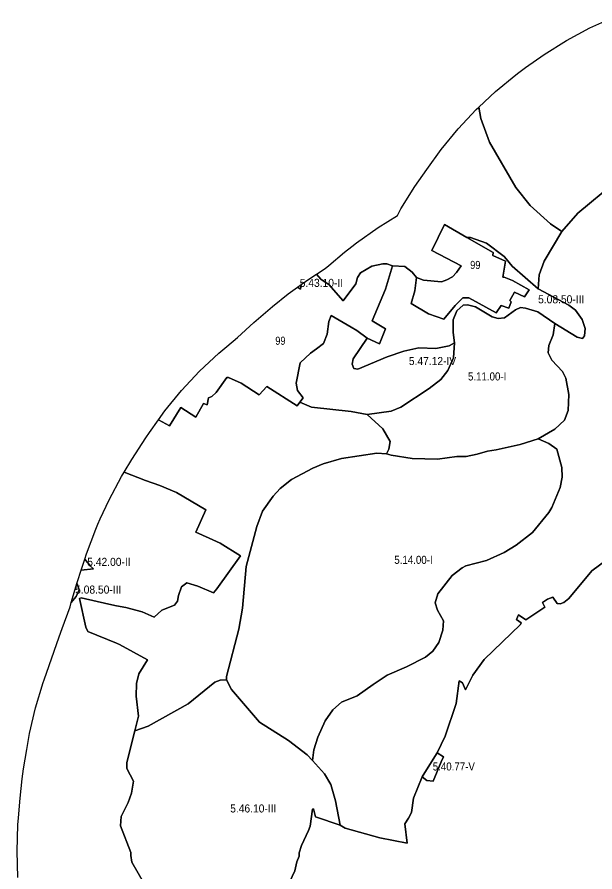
# Model space of a CAD drawing. Extents: x -591496 to -585489, y -1120610 to -1115685.
# Drawn here: x -591496 to -590065, y -1118038 to -1115920 of the extents above; entities that cross this region are included whole.
import ezdxf

# ---------------------------------------------------------------- set-up
doc = ezdxf.new("R2010")
doc.units = 0
doc.header["$LTSCALE"] = 8
doc.layers.add('40', color=7, linetype='Continuous', lineweight=25)
doc.layers.add('41', color=7, linetype='Continuous')

msp = doc.modelspace()

# ---------------------------------------------------------------- linework, layer by layer
at = {"layer": '40'}
for points in [[(-590015, -1116329.5), (-590106.5, -1116406), (-590146.5, -1116451.5), (-590174.5, -1116432), (-590225, -1116387), (-590260.5, -1116342), (-590325.5, -1116229.5), (-590347.5, -1116171), (-590352.159, -1116143.048), (-590311.076, -1116104.57), (-590260.491, -1116063.057), (-590253.1, -1116057.44), (-590236.32, -1116044.81), (-590190.52, -1116012.31), (-590134.95, -1115977.755), (-590077.239, -1115946.907), (-590017.633, -1115919.9)], [(-590130.5, -1116894.5), (-590129.5, -1116855.5), (-590136.5, -1116815), (-590144.5, -1116798), (-590171, -1116770), (-590180, -1116752), (-590178.5, -1116734), (-590168, -1116707), (-590164, -1116679.5), (-590108.5, -1116713), (-590095.5, -1116716.5), (-590090, -1116710), (-590089, -1116692), (-590096.5, -1116669.5), (-590112.5, -1116646.5), (-590129, -1116633.5), (-590205.5, -1116593.5), (-590203, -1116559), (-590190, -1116524.5), (-590146.5, -1116451.5), (-590106.5, -1116406), (-590015, -1116329.5)], [(-590037.5, -1117266.5), (-590072, -1117292), (-590129.5, -1117361), (-590141.5, -1117370.5), (-590150.5, -1117374), (-590158, -1117373), (-590169, -1117357.5), (-590182, -1117362.5), (-590194.5, -1117370.5), (-590188.5, -1117382), (-590236, -1117414), (-590253.5, -1117401), (-590259, -1117413), (-590247, -1117421.5), (-590248.5, -1117425.5), (-590339, -1117512), (-590367, -1117550.5), (-590385, -1117587.5), (-590392.5, -1117570), (-590401, -1117565), (-590408.5, -1117621), (-590435.5, -1117702), (-590455.5, -1117743), (-590457, -1117746), (-590492.5, -1117802.5), (-590514, -1117856), (-590518.5, -1117891), (-590526.5, -1117905.5), (-590535, -1117919), (-590530, -1117967.5), (-590597.5, -1117954), (-590683, -1117930), (-590696, -1117922.5), (-590707, -1117862.5), (-590719, -1117822), (-590734.5, -1117795), (-590764, -1117762.5), (-590760.5, -1117736), (-590751, -1117704.5), (-590732.5, -1117664), (-590713.5, -1117637), (-590692.5, -1117618), (-590653.5, -1117602), (-590614, -1117574), (-590579, -1117550.5), (-590531, -1117530.5), (-590484.5, -1117506.5), (-590466, -1117491), (-590451.5, -1117470), (-590441, -1117439), (-590440, -1117416.5), (-590454.5, -1117389.5), (-590460, -1117371.5), (-590454, -1117349), (-590418.5, -1117304), (-590393.5, -1117285), (-590384, -1117280), (-590333.5, -1117266.5), (-590289, -1117247), (-590260, -1117228.5), (-590219, -1117197.5), (-590179, -1117147.5), (-590171, -1117135), (-590150.5, -1117085.5), (-590145.5, -1117060.5), (-590146.5, -1117036), (-590159, -1116991), (-590179, -1116976.5), (-590205, -1116965.5), (-590164, -1116941), (-590140, -1116918.5), (-590130.5, -1116894.5)], [(-591342.5, -1117339.5), (-591347, -1117324.5), (-591347.697, -1117323.261), (-591346.221, -1117318.278), (-591337.303, -1117290.825), (-591307, -1117287), (-591314.5, -1117281), (-591328.334, -1117263.213), (-591328.261, -1117262.988), (-591324.11, -1117250.491), (-591301.059, -1117189.247), (-591295.803, -1117176.795), (-591289.923, -1117163.125), (-591268.173, -1117115.971), (-591237.325, -1117058.26), (-591231.026, -1117047.945), (-591178, -1117068), (-591142.5, -1117081), (-591101, -1117098.5), (-591028.5, -1117141), (-591053, -1117196), (-591020, -1117211.5), (-590993, -1117223.5), (-590942.5, -1117255), (-591001, -1117337), (-591009, -1117346.5), (-591048.5, -1117330), (-591075.5, -1117322), (-591088.5, -1117331.5), (-591096, -1117353.5), (-591098.5, -1117367.5), (-591106, -1117377), (-591137.5, -1117389.5), (-591156, -1117407), (-591186, -1117393.5), (-591227, -1117383.5), (-591250, -1117378.571), (-591269, -1117374.5), (-591337, -1117359), (-591341.5, -1117361), (-591326, -1117432), (-591321, -1117442.5), (-591250, -1117471.895), (-591242.5, -1117475), (-591172.5, -1117512.5), (-591194.5, -1117547.5), (-591200, -1117571.5), (-591201, -1117603), (-591195, -1117652.5), (-591204.5, -1117688.5), (-591224.5, -1117767), (-591224, -1117782.5), (-591207.5, -1117813.5), (-591212.5, -1117843.5), (-591221, -1117866), (-591238.5, -1117901), (-591240, -1117924.5), (-591214, -1117990), (-591214, -1117998), (-591212, -1118014.5), (-591149, -1118123.5)], [(-590408.5, -1117621), (-590401, -1117565), (-590392.5, -1117570), (-590385, -1117587.5), (-590367, -1117550.5), (-590339, -1117512), (-590248.5, -1117425.5), (-590247, -1117421.5), (-590259, -1117413), (-590253.5, -1117401), (-590236, -1117414), (-590188.5, -1117382), (-590194.5, -1117370.5), (-590182, -1117362.5), (-590169, -1117357.5), (-590158, -1117373), (-590150.5, -1117374), (-590141.5, -1117370.5), (-590129.5, -1117361), (-590072, -1117292), (-590037.5, -1117266.5)], [(-591493.809, -1118052.133), (-591495.95, -1117986.73), (-591493.809, -1117921.327), (-591492.534, -1117904.145), (-591488.524, -1117855.755), (-591483.385, -1117807.814), (-591479.753, -1117782.697), (-591472.253, -1117735.097), (-591465.225, -1117695.65), (-591450.366, -1117631.921), (-591431.37, -1117569.3), (-591428.989, -1117562.37), (-591391.829, -1117455.48), (-591384.383, -1117434.798), (-591364.374, -1117381.078), (-591361.731, -1117370.949), (-591349.5, -1117356), (-591342.5, -1117339.5)], [(-591149, -1118123.5), (-591212, -1118014.5), (-591214, -1117998), (-591214, -1117990), (-591240, -1117924.5), (-591238.5, -1117901), (-591221, -1117866), (-591212.5, -1117843.5), (-591207.5, -1117813.5), (-591224, -1117782.5), (-591224.5, -1117767), (-591204.5, -1117688.5), (-591171, -1117677), (-591072, -1117622), (-591006.5, -1117568.5), (-590992.5, -1117563.5), (-590977.5, -1117562), (-590964.5, -1117586), (-590895.5, -1117667), (-590823.5, -1117712.5), (-590777, -1117748), (-590764, -1117762.5), (-590734.5, -1117795), (-590719, -1117822), (-590707, -1117862.5), (-590696, -1117922.5), (-590757, -1117901.5), (-590761.5, -1117882), (-590764.5, -1117882.5), (-590770, -1117925), (-590774, -1117936), (-590791, -1117973), (-590797, -1117991.5), (-590797.5, -1117999.5), (-590803, -1118013.5), (-590808, -1118036), (-590827.5, -1118077.5)], [(-590827.5, -1118077.5), (-590808, -1118036), (-590803, -1118013.5), (-590797.5, -1117999.5), (-590797, -1117991.5), (-590791, -1117973), (-590774, -1117936), (-590770, -1117925), (-590764.5, -1117882.5), (-590761.5, -1117882), (-590757, -1117901.5), (-590696, -1117922.5), (-590683, -1117930), (-590597.5, -1117954), (-590530, -1117967.5), (-590535, -1117919), (-590526.5, -1117905.5), (-590518.5, -1117891), (-590514, -1117856), (-590492.5, -1117802.5), (-590481, -1117811.5), (-590465.5, -1117813.5), (-590445, -1117766), (-590440, -1117753.5), (-590455.5, -1117743), (-590435.5, -1117702), (-590408.5, -1117621)]]:
    msp.add_lwpolyline(points, dxfattribs=at)
for points in [[(-590174.5, -1116432), (-590146.5, -1116451.5), (-590190, -1116524.5), (-590203, -1116559), (-590205.5, -1116593.5), (-590269.5, -1116537), (-590284.5, -1116519), (-590289.5, -1116513), (-590333.5, -1116480.5), (-590373, -1116466), (-590381.5, -1116466), (-590437.5, -1116433.5), (-590468.5, -1116498.5), (-590396, -1116536), (-590407.5, -1116552.5), (-590417.5, -1116563.5), (-590431.5, -1116571), (-590444.5, -1116576), (-590489, -1116571.5), (-590506.5, -1116565), (-590517.5, -1116552), (-590535.5, -1116538), (-590566, -1116536), (-590580, -1116531), (-590590, -1116531.5), (-590617.5, -1116537), (-590645.5, -1116554), (-590652.5, -1116565), (-590657, -1116581), (-590688, -1116623.5), (-590712, -1116596), (-590722.5, -1116583.5), (-590743.5, -1116569), (-590754.2, -1116556.678), (-590732.937, -1116543.157), (-590723.896, -1116535.13), (-590685, -1116502.724), (-590666.71, -1116488.254), (-590655.021, -1116479.147), (-590601.83, -1116441.03), (-590553.856, -1116411.198), (-590545.055, -1116394.93), (-590510.5, -1116339.36), (-590481.028, -1116297.603), (-590445.083, -1116247.649), (-590403.57, -1116197.064), (-590358.837, -1116149.303), (-590352.159, -1116143.048), (-590347.5, -1116171), (-590325.5, -1116229.5), (-590260.5, -1116342), (-590225, -1116387)], [(-590381.5, -1116466), (-590316.5, -1116503.5), (-590317.5, -1116510.5), (-590286, -1116525), (-590293, -1116564.5), (-590289, -1116564.5), (-590268.5, -1116572.5), (-590227.5, -1116596), (-590239, -1116613), (-590263.5, -1116601.5), (-590275, -1116622), (-590272, -1116625.5), (-590277.5, -1116641.5), (-590297, -1116634.5), (-590309, -1116653), (-590376.5, -1116616), (-590391.5, -1116616), (-590410.5, -1116634.5), (-590439, -1116668.5), (-590477, -1116655), (-590519.5, -1116629.5), (-590511, -1116598), (-590506.5, -1116565), (-590489, -1116571.5), (-590444.5, -1116576), (-590431.5, -1116571), (-590417.5, -1116563.5), (-590407.5, -1116552.5), (-590396, -1116536), (-590468.5, -1116498.5), (-590437.5, -1116433.5)], [(-590205.5, -1116593.5), (-590129, -1116633.5), (-590112.5, -1116646.5), (-590096.5, -1116669.5), (-590089, -1116692), (-590090, -1116710), (-590095.5, -1116716.5), (-590108.5, -1116713), (-590164, -1116679.5), (-590206, -1116650.5), (-590236.5, -1116641), (-590248.5, -1116640), (-590261.5, -1116645.5), (-590288.5, -1116665), (-590304, -1116667), (-590319, -1116663), (-590360.5, -1116638), (-590380, -1116633), (-590390.5, -1116634), (-590407, -1116647.5), (-590415.5, -1116670), (-590416, -1116701.5), (-590412.5, -1116727.5), (-590425.5, -1116734.5), (-590458.5, -1116741), (-590500.5, -1116739.5), (-590537.5, -1116747.5), (-590579.5, -1116761.5), (-590652, -1116792.5), (-590662, -1116791), (-590666, -1116780), (-590663, -1116766.5), (-590628.5, -1116715.5), (-590598, -1116730), (-590583.5, -1116692.5), (-590616, -1116673), (-590583.5, -1116594.5), (-590566, -1116536), (-590535.5, -1116538), (-590517.5, -1116552), (-590506.5, -1116565), (-590511, -1116598), (-590519.5, -1116629.5), (-590477, -1116655), (-590439, -1116668.5), (-590410.5, -1116634.5), (-590391.5, -1116616), (-590376.5, -1116616), (-590309, -1116653), (-590297, -1116634.5), (-590277.5, -1116641.5), (-590272, -1116625.5), (-590275, -1116622), (-590263.5, -1116601.5), (-590239, -1116613), (-590227.5, -1116596), (-590268.5, -1116572.5), (-590289, -1116564.5), (-590293, -1116564.5), (-590286, -1116525), (-590317.5, -1116510.5), (-590316.5, -1116503.5), (-590381.5, -1116466), (-590373, -1116466), (-590333.5, -1116480.5), (-590289.5, -1116513), (-590284.5, -1116519), (-590269.5, -1116537)], [(-590566, -1116536), (-590583.5, -1116594.5), (-590616, -1116673), (-590583.5, -1116692.5), (-590598, -1116730), (-590628.5, -1116715.5), (-590654, -1116697), (-590668, -1116688.5), (-590717.5, -1116659.5), (-590724, -1116674.5), (-590727.5, -1116706), (-590736.5, -1116728.5), (-590754, -1116742), (-590769, -1116752.5), (-590794.5, -1116776.5), (-590805, -1116827.5), (-590801, -1116845.5), (-590787, -1116863.5), (-590795.5, -1116874), (-590802.5, -1116883.5), (-590877, -1116835), (-590896.5, -1116856), (-590940.5, -1116827.5), (-590972.5, -1116813.5), (-590976, -1116813.5), (-591003, -1116850.5), (-591013.5, -1116860), (-591021.5, -1116863.5), (-591025.5, -1116881), (-591034, -1116877.5), (-591053, -1116911), (-591090.5, -1116887.5), (-591118.5, -1116933), (-591146.006, -1116918.132), (-591130.123, -1116895.969), (-591088.61, -1116845.384), (-591043.877, -1116797.623), (-590996.116, -1116752.89), (-590976.698, -1116736.295), (-590950.146, -1116714.183), (-590909.506, -1116676.5), (-590898.045, -1116666.602), (-590863.455, -1116637.182), (-590824.331, -1116605.567), (-590801.138, -1116588.947), (-590793.5, -1116594), (-590792.557, -1116582.797), (-590771.14, -1116567.45), (-590754.2, -1116556.678), (-590743.5, -1116569), (-590722.5, -1116583.5), (-590712, -1116596), (-590688, -1116623.5), (-590657, -1116581), (-590652.5, -1116565), (-590645.5, -1116554), (-590617.5, -1116537), (-590590, -1116531.5), (-590580, -1116531)], [(-590792.557, -1116582.797), (-590793.5, -1116594), (-590801.138, -1116588.947)], [(-590164, -1116679.5), (-590168, -1116707), (-590178.5, -1116734), (-590180, -1116752), (-590171, -1116770), (-590144.5, -1116798), (-590136.5, -1116815), (-590129.5, -1116855.5), (-590130.5, -1116894.5), (-590140, -1116918.5), (-590164, -1116941), (-590205, -1116965.5), (-590250, -1116979), (-590309, -1116992), (-590331, -1116995.5), (-590356.5, -1117003.5), (-590383.5, -1117008.5), (-590406.5, -1117009), (-590454.5, -1117015.5), (-590517, -1117013.5), (-590569, -1117005.5), (-590581, -1117002), (-590575, -1116991), (-590571.5, -1116972), (-590589.5, -1116940.5), (-590628.5, -1116905), (-590569, -1116896.5), (-590545, -1116886.5), (-590475, -1116840.5), (-590446, -1116818), (-590428.5, -1116795.5), (-590415, -1116764), (-590412.5, -1116727.5), (-590416, -1116701.5), (-590415.5, -1116670), (-590407, -1116647.5), (-590390.5, -1116634), (-590380, -1116633), (-590360.5, -1116638), (-590319, -1116663), (-590304, -1116667), (-590288.5, -1116665), (-590261.5, -1116645.5), (-590248.5, -1116640), (-590236.5, -1116641), (-590206, -1116650.5)], [(-590628.5, -1116715.5), (-590663, -1116766.5), (-590666, -1116780), (-590662, -1116791), (-590652, -1116792.5), (-590579.5, -1116761.5), (-590537.5, -1116747.5), (-590500.5, -1116739.5), (-590458.5, -1116741), (-590425.5, -1116734.5), (-590412.5, -1116727.5), (-590415, -1116764), (-590428.5, -1116795.5), (-590446, -1116818), (-590475, -1116840.5), (-590545, -1116886.5), (-590569, -1116896.5), (-590628.5, -1116905), (-590668, -1116897), (-590766.5, -1116886.5), (-590795.5, -1116874), (-590787, -1116863.5), (-590801, -1116845.5), (-590805, -1116827.5), (-590794.5, -1116776.5), (-590769, -1116752.5), (-590754, -1116742), (-590736.5, -1116728.5), (-590727.5, -1116706), (-590724, -1116674.5), (-590717.5, -1116659.5), (-590668, -1116688.5), (-590654, -1116697)], [(-590940.5, -1116827.5), (-590896.5, -1116856), (-590877, -1116835), (-590802.5, -1116883.5), (-590795.5, -1116874), (-590766.5, -1116886.5), (-590668, -1116897), (-590628.5, -1116905), (-590589.5, -1116940.5), (-590571.5, -1116972), (-590575, -1116991), (-590581, -1117002), (-590604.5, -1117000.5), (-590692, -1117014), (-590737.5, -1117027), (-590763.5, -1117037.5), (-590816, -1117066), (-590844, -1117088), (-590861.5, -1117107.5), (-590888, -1117144), (-590902, -1117182.5), (-590928.5, -1117281.5), (-590937.5, -1117385), (-590947, -1117436.5), (-590977.5, -1117554), (-590977.5, -1117562), (-590992.5, -1117563.5), (-591006.5, -1117568.5), (-591072, -1117622), (-591171, -1117677), (-591204.5, -1117688.5), (-591195, -1117652.5), (-591201, -1117603), (-591200, -1117571.5), (-591194.5, -1117547.5), (-591172.5, -1117512.5), (-591242.5, -1117475), (-591250, -1117471.895), (-591321, -1117442.5), (-591326, -1117432), (-591341.5, -1117361), (-591337, -1117359), (-591269, -1117374.5), (-591250, -1117378.571), (-591227, -1117383.5), (-591186, -1117393.5), (-591156, -1117407), (-591137.5, -1117389.5), (-591106, -1117377), (-591098.5, -1117367.5), (-591096, -1117353.5), (-591088.5, -1117331.5), (-591075.5, -1117322), (-591048.5, -1117330), (-591009, -1117346.5), (-591001, -1117337), (-590942.5, -1117255), (-590993, -1117223.5), (-591020, -1117211.5), (-591053, -1117196), (-591028.5, -1117141), (-591101, -1117098.5), (-591142.5, -1117081), (-591178, -1117068), (-591231.026, -1117047.945), (-591211.636, -1117016.194), (-591177.106, -1116962.664), (-591168.24, -1116949.16), (-591146.006, -1116918.132), (-591118.5, -1116933), (-591090.5, -1116887.5), (-591053, -1116911), (-591034, -1116877.5), (-591025.5, -1116881), (-591021.5, -1116863.5), (-591013.5, -1116860), (-591003, -1116850.5), (-590976, -1116813.5), (-590972.5, -1116813.5)], [(-590764, -1117762.5), (-590777, -1117748), (-590823.5, -1117712.5), (-590895.5, -1117667), (-590964.5, -1117586), (-590977.5, -1117562), (-590977.5, -1117554), (-590947, -1117436.5), (-590937.5, -1117385), (-590928.5, -1117281.5), (-590902, -1117182.5), (-590888, -1117144), (-590861.5, -1117107.5), (-590844, -1117088), (-590816, -1117066), (-590763.5, -1117037.5), (-590737.5, -1117027), (-590692, -1117014), (-590604.5, -1117000.5), (-590581, -1117002), (-590569, -1117005.5), (-590517, -1117013.5), (-590454.5, -1117015.5), (-590406.5, -1117009), (-590383.5, -1117008.5), (-590356.5, -1117003.5), (-590331, -1116995.5), (-590309, -1116992), (-590250, -1116979), (-590205, -1116965.5), (-590179, -1116976.5), (-590159, -1116991), (-590146.5, -1117036), (-590145.5, -1117060.5), (-590150.5, -1117085.5), (-590171, -1117135), (-590179, -1117147.5), (-590219, -1117197.5), (-590260, -1117228.5), (-590289, -1117247), (-590333.5, -1117266.5), (-590384, -1117280), (-590393.5, -1117285), (-590418.5, -1117304), (-590454, -1117349), (-590460, -1117371.5), (-590454.5, -1117389.5), (-590440, -1117416.5), (-590441, -1117439), (-590451.5, -1117470), (-590466, -1117491), (-590484.5, -1117506.5), (-590531, -1117530.5), (-590579, -1117550.5), (-590614, -1117574), (-590653.5, -1117602), (-590692.5, -1117618), (-590713.5, -1117637), (-590732.5, -1117664), (-590751, -1117704.5), (-590760.5, -1117736)], [(-591307, -1117287), (-591337.303, -1117290.825), (-591328.334, -1117263.213), (-591314.5, -1117281)], [(-591361.731, -1117370.949), (-591361.066, -1117368.401), (-591347.697, -1117323.261), (-591347, -1117324.5), (-591342.5, -1117339.5), (-591349.5, -1117356)], [(-590492.5, -1117802.5), (-590457, -1117746), (-590455.5, -1117743), (-590440, -1117753.5), (-590445, -1117766), (-590465.5, -1117813.5), (-590481, -1117811.5)]]:
    msp.add_lwpolyline(points, close=True, dxfattribs=at)

# ---------------------------------------------------------------- texts
at = {"layer": '41'}
for s, width, p in [('99', 0.85, (-590373.5, -1116544.125)), ('5.43.10-II', 0.95, (-590795.732, -1116588.581)), ('5.08.50-III', 0.95, (-590205.219, -1116629.25)), ('99', 0.85, (-590856.313, -1116732)), ('5.47.12-IV', 0.95, (-590525.406, -1116782.25)), ('5.11.00-I', 0.9, (-590379, -1116820.438)), ('5.42.00-II', 0.95, (-591322.125, -1117280)), ('5.14.00-I', 0.9, (-590561.5, -1117274.938)), ('5.08.50-III', 0.95, (-591352.125, -1117348.688)), ('5.40.77-V', 0.9, (-590466.25, -1117787.063)), ('5.46.10-III', 0.95, (-590968, -1117891.125))]:
    msp.add_text(s, height=20, dxfattribs=dict(at, width=width)).set_placement(p)

doc.saveas('drawing.dxf')
